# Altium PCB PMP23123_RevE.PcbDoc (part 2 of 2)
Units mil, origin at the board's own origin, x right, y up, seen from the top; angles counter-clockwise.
Board outline 4000 x 3800 mil, 4 copper layers (Top Layer, Layer 1, Layer 2, Bottom Layer), stack 76 mil thick; 128 components, 55 nets, 360 pads, 207 vias.
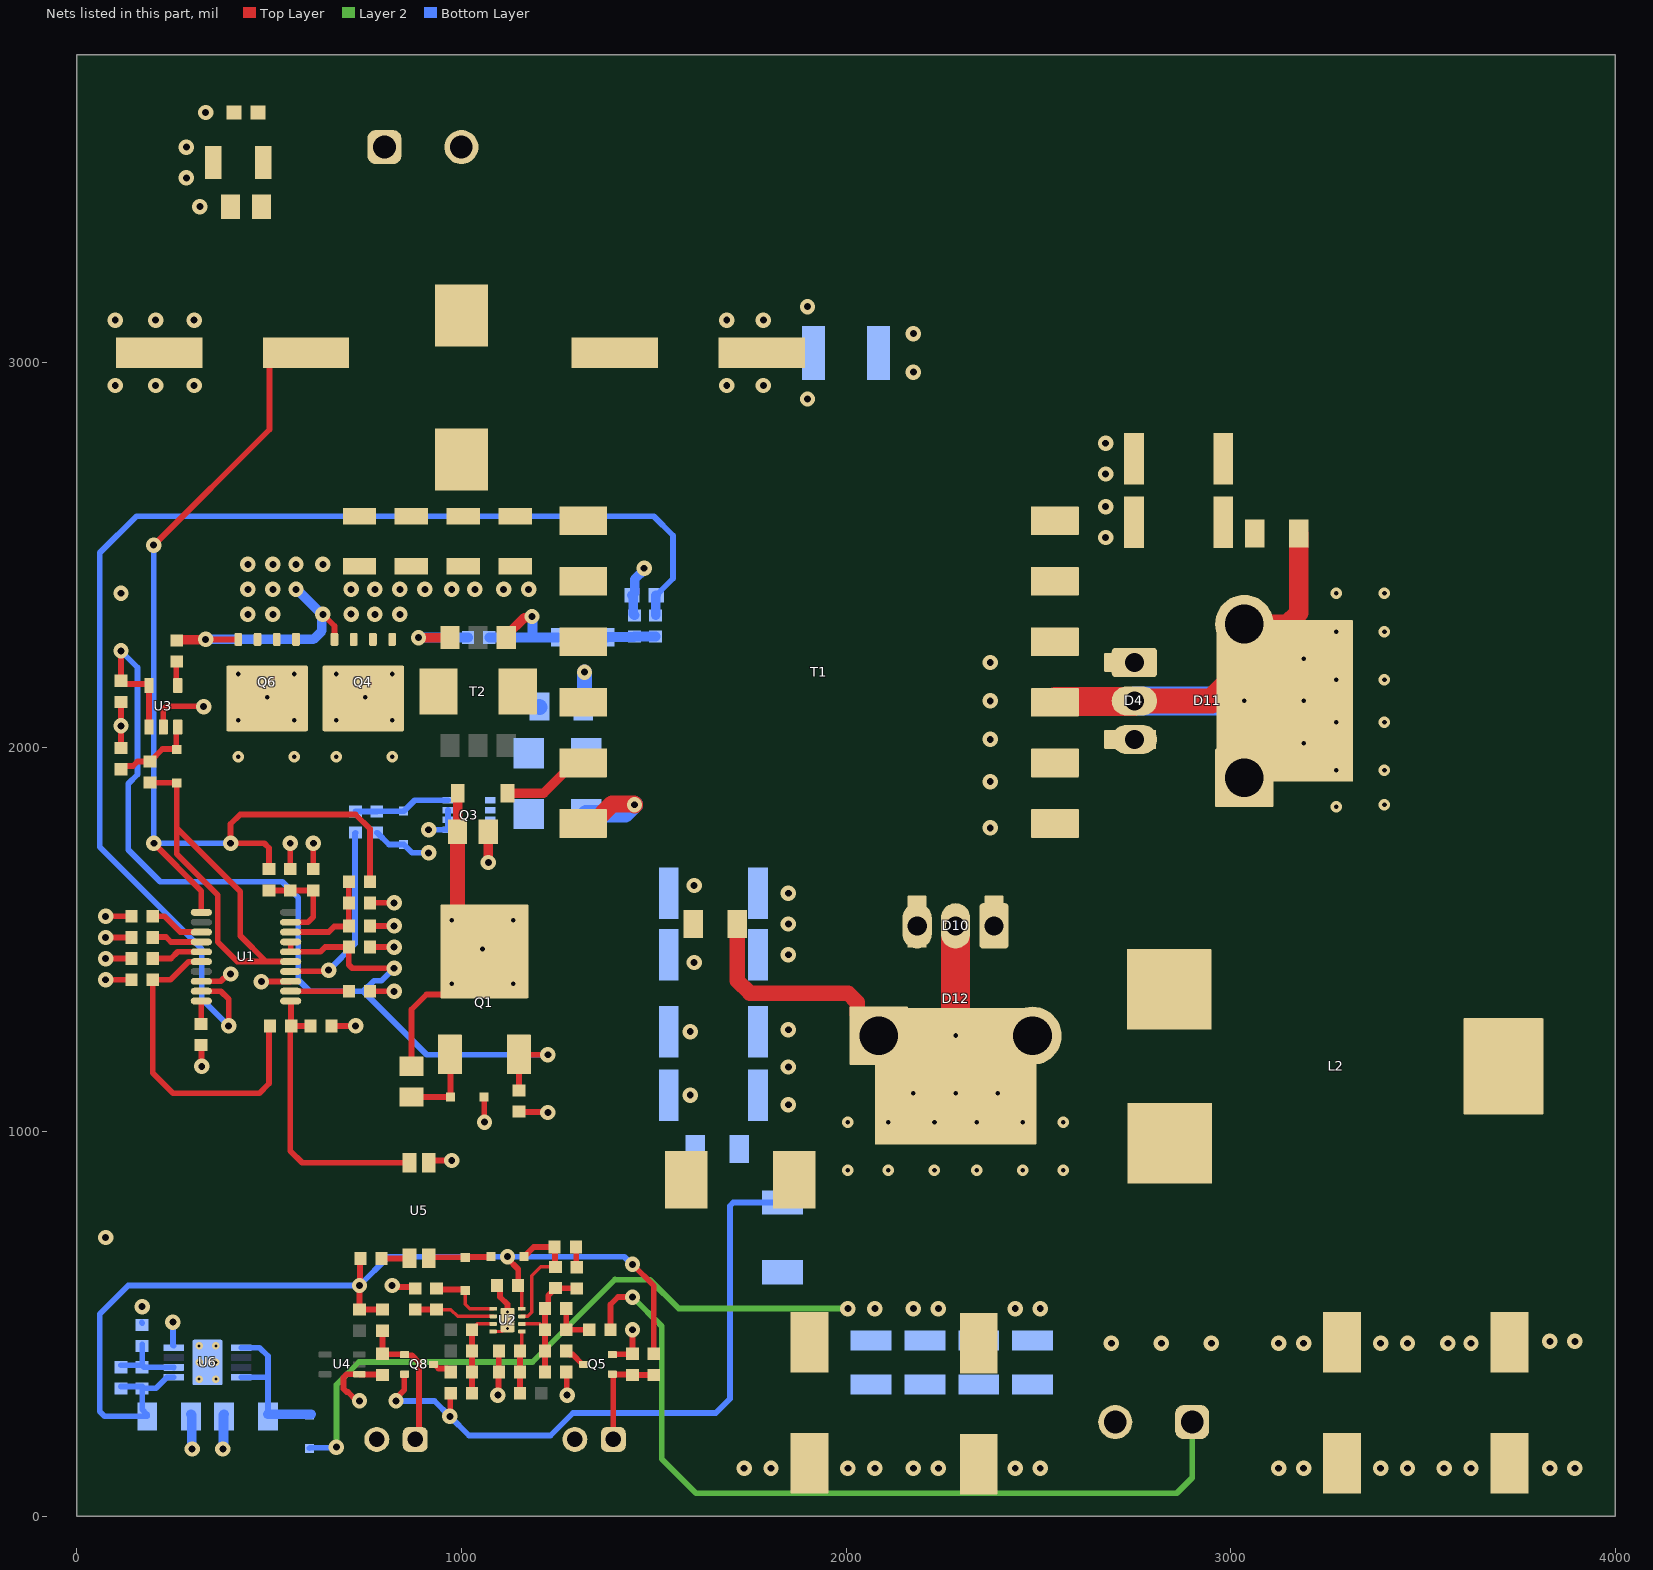
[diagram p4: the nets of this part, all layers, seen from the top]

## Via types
v1: diameter 40, hole 18, Top Layer to Bottom Layer, 148 vias
v2: diameter 30, hole 12, Top Layer to Bottom Layer, 51 vias
v3: diameter 19.68, hole 7.87, Top Layer to Bottom Layer, tented both sides, 4 vias
v4: diameter 19.68, hole 7.87, Top Layer to Bottom Layer, 4 vias

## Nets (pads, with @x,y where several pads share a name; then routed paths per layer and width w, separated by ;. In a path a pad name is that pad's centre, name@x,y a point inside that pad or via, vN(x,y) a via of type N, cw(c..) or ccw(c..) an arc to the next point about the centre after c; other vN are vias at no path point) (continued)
GND: C7.2 C8.2 C16.1 C17.1 C18.1 C19.1 C21.1 C30.2 C32.1 C37.1 C38.1 C100.2 C101.2 J2.2 J3.2 J4.2 L2.1 Q5.2 R3.2 R16.2 R18.2 R21.2 R30.2 R33.2 R36.2 U2.4 U2.9 U4.1 U6.4 U6.9@340,400 | length 913.7
  Top Layer w9: U2.4@1082.6,480.47 1104.25,480.47 1112.13,488.35 v4(1120,488.35)
  Top Layer w15: v1(735,300) 728.24,300 705.18,323.06 702.01,323.06 693.23,331.84 693.23,360.62 702.01,369.41 U4.1@734.29,369.41 734.63,369.41 735,369.04 793.41,369.04 R33.2@795,367.44 ; v1(820,600) 823.72,596.28 876.28,596.28 R30.2@880,592.56 ; C37.1@1092.44,600 1100.69,591.75 1100.69,570.48 1120,551.17 v4(1120,531.65) ; v1(1095,315) 1096.22,316.22 1096.22,373.78 C30.2@1097.44,375 R21.2@1097.44,430 ; R16.2@1272.56,375 1273.78,373.78 1273.78,316.22 v1(1275,315) ; Q5.2@1392.4,420.59 1393.39,421.57 1444.02,421.57 R18.2@1445,422.56 v1(1445,485)
  Bottom Layer w15: R36.2@168.78,503.78 R36.2@170,502.56 ; v1(250,505) 250,444.74 251.36,443.39 U6.4@252.4,443.39
  Bottom Layer w25: C38.1@297.09,265 298.54,263.54 298.54,176.46 v1(300,175) ; v1(380,175) 381.46,176.46 381.46,263.54 C32.1@382.91,265
  other v1: 1735,125 1805,125 2005,125 2075,125 2175,125 2240,125 2440,125 2505,125 3125,125 3190,125 3390,125 3460,125 3555,125 3625,125 3830,125 3895,125 170,545 75,725 2175,2975 2175,3075
  other v3: 318.35,356.69 361.65,356.69 318.35,443.31 361.65,443.31
  other v4: 318.35,400 361.65,400
ISNS: C41.1 D4.1 D4.3 D10.1 D10.3 D11.1 D11.3 D12.1 D12.3 Q8.2 R3.1 R34.2 R37.2 R38.2 R39.2 R40.2 R41.2 R42.2 T1.8 T1.10 T1.11 T1.12 | length 1726.6
  Top Layer w15: v1(830,300) 830,306.76 851.61,328.38 851.61,368.43 Q8.2@852.6,369.41 ; v1(970,260) 971.22,261.22 971.22,318.78 R34.2@972.44,320
  Bottom Layer w15: v1(830,300) 930,300 v1(970,260) 1020,210 1231.52,210 1289.86,268.35 1661.22,268.35 1698.31,305.43 1698.31,806.76 1707.09,815.55 R3.1@1835,815.55
  other v1: 1850,1070 1850,1168.34 1850,1265 1850,1460 1850,1540 1850,1620 2375,1790 2375,1910 2375,2020 2375,2120 2375,2220 2675,2545 2675,2625 2675,2710 2675,2790
NetC2_1: C2.1 U1.12 | length 151.5
  Top Layer w15: U1.12@556.14,1365.43 556.36,1365.22 707.22,1365.22 C2.1@707.44,1365
NetC3_2: C3.2 D1.1 Q1.2 R1.2 | length 734.3
  Top Layer w15: R1.2@870,1170 870,1317.48 909.11,1356.59 953.33,1356.59 Q1.2@1060,1463.27
  Top Layer w25: C3.2@990,1780 990.27,1780.27 990.27,1879.73 D1.1@990.53,1880
  Top Layer w40: v2(975,1550) 990,1565 C3.2@990,1780
  other v2: 975,1385 1135,1385 1055,1475 1135,1550
NetC12_2: C12.2 C13.2 C14.2 C15.2 L1.2 T1.1 T1.2
NetC20_1: C20.1 T1.3 T1.4 T2.8 | length 91.2
  Bottom Layer w40: C20.1@1317.09,2105 1320,2107.91 v1(1320,2195)
NetC20_2: C20.2 D13.1 D14.2 | length 1.5
  Bottom Layer w40: C20.2@1202.91,2105 C20.2@1203.96,2103.96
NetC22_1: C22.1 D6.2 Q3.4 R9.1 | length 252.1
  Bottom Layer w15: C22.1@725,1832.56 R9.1@780,1832.56 780.37,1832.93 849.63,1832.93 D6.2@850,1833.31 878.46,1861.77 Q3.4@965,1861.77
NetC22_2: C22.2 U1.14 | length 486.7
  Top Layer w15: U1.14@556.14,1416.61 556.66,1417.13 652.13,1417.13 v1(655,1420)
  Bottom Layer w15: v1(655,1420) 723.66,1488.66 723.66,1776.1 C22.2@725,1777.44
NetC23_2: C23.2 R5.1 R10.1 U1.19 | length 248.8
  Top Layer w15: R5.1@500,1627.44 R10.1@555,1627.44 C23.2@615,1627.44 615,1558.03 601.54,1544.57 U1.19@556.14,1544.57
NetC24_2: C24.2 R6.1 R14.1 U1.18 | length 272.9
  Top Layer w15: U1.18@556.14,1518.98 655.12,1518.98 669.45,1533.31 705.75,1533.31 C24.2@707.44,1535 R14.1@707.44,1595 R6.1@707.44,1650
NetC25_1: C25.1 C27.1 C102.1 R7.2 R12.1 R16.1 U2.6 | length 351.3
  Top Layer w9: U2.6@1157.4,500.16 1203.27,500.16 R7.2@1217.44,485.98
  Top Layer w15: R16.1@1217.44,375 R12.1@1217.44,430 R7.2@1217.44,485 1217.44,485.98 C102.1@1217.44,540 1225.69,548.25 1225.69,573.8 1235.77,583.88 1235.77,584.86 1244.02,593.11 C25.1@1245,593.11 1245.33,592.78 1299.67,592.78 C27.1@1300,592.44
NetC25_2: C25.2 D8.1 R17.1 U2.7 | length 338.3
  Top Layer w9: U2.7@1157.4,519.84 1157.82,520.26 1172.51,520.26 1182.8,530.55 1182.8,625.85 1206.28,649.33 C25.2@1243.9,649.33
  Top Layer w15: D8.1@1163.31,675 1188.31,700 R17.1@1242.44,700 1243.72,698.72 1243.72,649.51 1243.9,649.33 C25.2@1245,648.23
NetC26_2: C26.2 R2.2 U1.9 | length 3295.1
  Top Layer w15: U1.9@323.86,1365.43 374.57,1365.43 395,1345 v1(395,1275)
  Bottom Layer w15: v1(395,1275) 325,1345 325,1475 60,1740 60,2505 154.96,2599.96 1500.04,2599.96 1550,2550 1550,2438.5 1518.68,2407.19 1518.68,2406.2 1507.48,2395 C26.2@1506.5,2395
  Bottom Layer w25: R2.2@1505,2342.56 1505.75,2343.31 1505.75,2394.25 C26.2@1506.5,2395
NetC27_2: C27.2 R17.2 | length 53.5
  Top Layer w15: R17.2@1297.56,700 1298.78,698.78 1298.78,648.78 C27.2@1300,647.56
NetC28_2: C28.2 R28.1 U1.11 U5.4 | length 764.2
  Top Layer w15: U1.11@556.14,1339.84 556.85,1339.13 556.85,1275.71 R28.1@557.56,1275 ; C28.2@607.44,1275 R28.1@557.56,1275 ; U5.4@865,919.02 585.98,919.02 555,950 555,1272.44 R28.1@557.56,1275
NetC30_1: C30.1 R19.1 R21.1 U2.5 | length 162.5
  Top Layer w9: R21.1@1152.56,430 1157.4,434.84 U2.5@1157.4,480.47
  Top Layer w15: R19.1@1152.44,320 1152.5,320.06 1152.5,374.94 C30.1@1152.56,375 R21.1@1152.56,430
NetC31_1: C31.1 D7.2 R26.2 U3.3 | length 229.1
  Top Layer w15: C31.1@115,1942.44 123.25,1950.69 145.89,1950.69 157.76,1962.56 R26.2@190,1962.56 190.98,1962.56 223.21,1994.78 258.52,1994.78 D7.2@258.7,1994.61 ; U3.3@258.7,2054.57 D7.2@258.7,1994.61 ; D7.2@260,1993.31 D7.2@258.7,1994.61 ; U3.3@261.83,2051.44 U3.3@263.13,2050.14
NetC32_2: C32.2 D100.1 U6.5 U6.8 | length 411.8
  Bottom Layer w15: U6.8@427.6,361.61 496.63,361.61 497.13,362.11 ; U6.5@427.6,438.39 475.35,438.39 497.13,416.61 497.13,362.11 ; C32.2@497.13,264.96 497.13,362.11
  Bottom Layer w25: C32.2@497.13,264.96 D100.1@609,264.96
NetC33_2: C33.2 R28.2 U1.6 | length 873.9
  Top Layer w15: U1.6@323.86,1442.2 323.34,1441.68 290.59,1441.68 243.9,1395 C33.2@197.56,1395 197.56,1152.44 250,1100 475,1100 500,1125 500,1272.56 R28.2@502.44,1275
NetC34_1: C34.1 R30.1 U2.2 | length 210
  Top Layer w9: C34.1@935,537.44 935.12,537.56 972.44,537.56 990.16,519.84 U2.2@1082.6,519.84
  Top Layer w15: R30.1@880,537.44 C34.1@935,537.44
NetC34_2: C34.2 D9.1 U2.1 | length 190.3
  Top Layer w9: D9.1@1010,586.69 1010,551.34 1021.81,539.53 U2.1@1082.6,539.53
  Top Layer w15: C34.2@935,592.56 937.93,589.63 1007.07,589.63 D9.1@1010,586.69
NetC35_2: C35.2 R29.1 R36.1 U6.2 | length 194.5
  Bottom Layer w15: C35.2@115,392.56 R29.1@170,392.56 ; R36.1@170,447.44 R36.1@170,442.44 R29.1@170,392.56 ; U6.2@252.4,387.2 252.22,387.38 175.18,387.38 R29.1@170,392.56
NetC36_1: C36.1 R32.2 R34.1 R35.2 U2.3 | length 226.9
  Top Layer w9: C36.1@1027.56,485 1027.56,485.98 1041.73,500.16 U2.3@1082.6,500.16
  Top Layer w15: R34.1@1027.56,320 R32.2@1027.56,375 R35.2@1027.56,430 C36.1@1027.56,485
NetC39_1: C39.1 R37.1 R38.1
NetC40_1: C40.1 R39.1 R40.1
  other v1: 1605,1440 1605,1640
NetC41_2: C41.2 D2.1 R41.1 R42.1
  other v1: 1595,1095 1595,1260
NetC102_2: C102.2 R4.1 R7.1 | length 114.9
  Top Layer w15: C102.2@1272.56,540 R7.1@1272.56,485 R4.1@1332.44,485
NetD1_2: D1.2 T1.5 | length 230
  Top Layer w25: D1.2@1119.47,1880 1213.43,1880 1292.2,1958.78 T1.5@1316.81,1958.78
NetD3_1: D3.1 Q1.1 R1.1 | length 213.4
  Top Layer w15: R1.1@870,1090 D3.1@971.69,1090 971.69,1199.68 Q1.1@970.24,1201.14
NetD5_1: D5.1 R2.1 R11.1 | length 126.5
  Bottom Layer w25: D5.1@1379.47,2285 1380.69,2286.22 1448.78,2286.22 R11.1@1450,2287.44 R2.1@1505,2287.44
NetD5_2: D5.2 R8.2 T2.1 | length 325.7
  Top Layer w25: T2.1@1116.5,2284.45 1116.5,2289.45 1163.63,2336.58 1180.63,2336.58 v1(1183.5,2339.45)
  Bottom Layer w25: R8.2@1072.56,2285 1185,2285 ; v1@1185,2340 1185,2285 ; D5.2@1250.53,2285 1185,2285
NetD7_1: D7.1 R26.1 U1.15 | length 1180.8
  Top Layer w15: R26.1@190,1907.44 190.37,1907.07 259.63,1907.07 D7.1@260,1906.69 260,1789.8 ; U1.15@555.62,1442.72 491.73,1442.72 ; 260,1789.8 260,1722.35 366.79,1615.56 366.79,1493.23 417.3,1442.72 491.73,1442.72 ; 260,1789.8 425,1624.8 425,1509.45 491.73,1442.72
NetD8_2: D8.2 D9.2 U5.2 | length 163.4
  Top Layer w15: U5.2@915,670.98 917.32,673.31 D9.2@1010,673.31 1010.85,674.15 1075.85,674.15 D8.2@1076.69,675
NetD13_2: D13.2 Q3.5 Q3.6 Q3.7 Q3.8
NetJ3_1: J3.1 Q5.1 R15.2 R18.1 | length 277.2
  Top Layer w15: Q5.1@1392.4,369.41 1393.25,369.41 Q5.1@1394.23,368.43 ; J3.1@1395,200 1395,367.66 Q5.1@1394.23,368.43 ; R15.2@1500,367.44 R18.1@1445,367.44 1444.02,368.43 Q5.1@1394.23,368.43
NetJ4_1: J4.1 Q8.1 R31.2 R33.1 | length 368.4
  Top Layer w15: R31.2@795,482.44 R33.1@795,422.56 795.98,421.57 851.61,421.57 Q8.1@852.6,420.59 854.35,418.84 871.16,418.84 890,400 890,210 J4.1@880,200
NetQ4_4: Q4.4 Q6.4 R24.1 | length 690.7
  Top Layer w15: v1(335,2280) Q6.4@420,2280 ; v1(640,2345) 670,2315 Q4.4@670,2280
  Top Layer w25: R24.1@260,2277.56 261.22,2278.78 333.78,2278.78 v1(335,2280)
  Bottom Layer w25: v1(335,2280) 615,2280 637.13,2302.13 637.13,2342.13 v1(640,2345) 637.5,2345 572.5,2410 v1(570,2410)
NetQ4_5: Q4.5 Q4.6 Q4.7 Q4.8 Q4.9@745,2126.46 Q6.5 Q6.6 Q6.7 Q6.8 Q6.9@495,2126.46 T2.7
  other v2: 420,1975 565,1975 675,1975 820,1975 420,2070 565,2070 675,2070 820,2070 495,2130 750,2130 420,2190 565,2190 675,2190 820,2190
NetQ5_3: Q5.3 R12.2 | length 60.1
  Top Layer w15: R12.2@1272.56,430 1272.56,429.02 1280.81,420.77 1289.27,420.77 1315.04,395 Q5.3@1317.6,395
NetQ8_3: Q8.3 R32.1 | length 53.9
  Top Layer w15: Q8.3@927.4,395 929.96,395 940.73,384.23 964.19,384.23 972.44,375.98 R32.1@972.44,375
NetR13_1: R13.1 U1.3 | length 143.3
  Top Layer w15: R13.1@197.56,1560 228.31,1560 269.33,1518.98 U1.3@323.86,1518.98
NetR20_2: R20.2 U1.4 | length 131.9
  Top Layer w15: R20.2@197.56,1505 198.51,1505.95 232.24,1505.95 244.81,1493.39 U1.4@323.86,1493.39
NetR23_2: R23.2 U1.5 | length 133.7
  Top Layer w15: R23.2@197.56,1450 244.81,1450 262.6,1467.8 U1.5@323.86,1467.8
NetR24_2: R24.2 U3.4 | length 59.4
  Top Layer w15: U3.4@258.7,2165.43 258.7,2221.14 R24.2@260,2222.44 ; U3.4@261.83,2159.71 U3.4@263.13,2161.01
NetR25_2: R25.2 U1.10 | length 59.9
  Top Layer w15: R25.2@323.34,1280.31 323.6,1280.57 323.6,1339.58 U1.10@323.86,1339.84 U1.10@323.78,1339.92
NetR27_2: R27.2 U5.1 | length 72.8
  Top Layer w15: R27.2@792.56,670 864.02,670 U5.1@865,670.98
P_BIAS: C1.2 C4.2 C29.1 Q1.3 U1.16 U1.17 U3.1 U3.5 | length 2861
  Top Layer w15: v1(115,2250) 115,2173.54 124.41,2164.13 182.6,2164.13 U3.5@183.25,2163.48 ; U3.1@187.67,2052.09 U3.5@187.67,2159.06 ; U1.17@556.14,1493.39 U1.16@556.14,1467.8 633.7,1467.8 645.91,1480 C4.2@707.44,1480 707.44,1433.79 716.23,1425 v1(825,1425) ; Q1.3@1149.76,1201.14 Q1.3@1150,1200.91 ; C1.2@1150,1107.56 Q1.3@1150,1200.91 ; v1(1225,1200) 1150.91,1200 Q1.3@1150,1200.91
  Bottom Layer w15: v1(115,2250) 157.76,2207.24 157.76,1928.66 133.7,1904.61 133.7,1733.06 216.76,1650 534.33,1650 575.67,1608.66 575.67,1395 605.67,1365 745,1365 ; v1(825,1425) 792.61,1392.61 772.61,1392.61 745,1365 ; v1(1225,1200) 910,1200 745,1365
PGND: C1.1 C2.2 C3.1 C4.1 C5.2 C6.2 C9.1 C10.1 C11.1 C12.1 C13.1 C14.1 C15.1 C21.2 C23.1 C24.1 C26.1 C28.1 C29.2 C31.2 C33.1 D3.2 D6.1 D14.1 J1.2 Q3.1 Q3.2 Q3.3 Q4.1 Q4.2 Q4.3 Q6.1 Q6.2 Q6.3 R8.1 R9.2 R10.2 R11.2 R13.2 R14.2 R20.1 R23.1 R25.1 T1.6 T2.3 U1.8 U1.13 U3.2 U5.3 | length 2471
  Top Layer w10: R20.1@135.55,1511.89 R20.1@142.44,1505 ; C13.1@850,2472.87 852.83,2470.04 C13.1@870,2470.04 879.96,2480 C13.1@889.68,2480 ; C14.1@1005,2470.04 1006.97,2472.01 C14.1@1024.68,2472.01
  Top Layer w15: v1(75,1395) C33.1@142.44,1395 ; v1(75,1450) R23.1@142.44,1450 ; v1(75,1505) R20.1@142.44,1505 ; v1(75,1560) R13.2@142.44,1560 ; C31.2@115,1997.56 v1(115,2055) ; C29.2@115,2117.44 v1(115,2055) ; v1@115.43,2055.43 v1(115,2055) ; U3.2@225.07,2052.09 225.07,2097.37 233.93,2106.22 v1@325.47,2106.22 ; 307.09,2106.22 v1@325.47,2106.22 ; R25.1@323.34,1225.2 324.17,1224.37 324.17,1170.83 v1(325,1170) ; U1.8@323.86,1391.02 374.26,1391.02 393.24,1410 v1(400,1410) ; v1@328.2,2103.49 v1@325.47,2106.22 ; v1(480,1390) 480.51,1390.51 555.63,1390.51 U1.13@556.14,1391.02 ; R10.2@555,1682.56 v1(555,1750) ; C23.1@615,1682.56 v1(615,1750) ; C28.1@662.56,1275 v1(725,1275) ; C2.2@762.56,1365 v1(825,1365) ; C4.1@762.56,1480 v1(825,1480) ; C24.1@762.56,1535 v1(825,1535) ; R14.2@762.56,1595 v1(825,1595) ; U5.3@915,919.02 920.98,925 v1(975,925) ; D3.2@1058.31,1090 1059.15,1089.15 1059.15,1025.85 v1(1060,1025) ; C1.1@1150,1052.44 1151.22,1051.22 1223.78,1051.22 v1(1225,1050)
  Top Layer w25: v1(888.5,2284.45) T2.3@970.5,2284.45 ; v1(1070,1700) C3.1@1070,1780
  Top Layer w45: T1.6@1316.81,1801.3 1341.42,1801.3 1392.36,1852.24 1447.76,1852.24 v1(1450,1850)
  Bottom Layer w15: R9.2@780,1777.44 780.98,1777.44 811.73,1746.69 D6.1@850,1746.69 871.69,1725 v1(915,1725) ; v1(915,1785) Q3.1@965,1785 Q3.2@965,1810.59 Q3.3@965,1836.18
  Bottom Layer w25: v1@900,2285 R8.1@1017.44,2285 ; R11.2@1450,2342.56 1446.75,2345.81 1446.75,2391.75 C26.1@1443.5,2395 1444.49,2395 1450.69,2401.2 1450.69,2436.63 1475,2460.94 v1(1475,2465)
  Bottom Layer w45: D14.1@1325,1826.26 1426.26,1826.26 v1(1450,1850)
  other v1: 330,2105 445,2345 510,2345 775,2345 840,2345 713.35,2345.81 115,2400 445,2410 510,2410 713.35,2410 775,2410 840,2410 905,2410 975,2410 1035,2410 1110,2410 1175,2410 445,2475 510,2475 570,2475 640,2475 1900,2905 100,2940 205,2940 305,2940 1690,2940 1785,2940 100,3110 205,3110 305,3110 1690,3110 1785,3110 1900,3145 320,3405 285,3480 285,3560 335,3650
S_BIAS: C35.1 C37.2 C38.2 R15.1 R22.1 R27.1 R29.2 R31.1 U2.8 U6.1 | length 2667.6
  Top Layer w9: C37.2@1147.56,600 1157.4,590.16 U2.8@1157.4,539.53
  Top Layer w15: R27.1@737.44,670 736.22,668.78 736.22,601.22 v1(735,600) R22.1@735,537.56 R31.1@795,537.56 ; v1(1120,675) 1120,670.01 1147.56,642.45 C37.2@1147.56,600 ; v1(1445,655) 1500,600 1500,501.46 ; R15.1@1500,422.56 1500,501.46 ; 1501.46,500 1500,501.46
  Bottom Layer w15: C35.1@115,337.44 R29.2@170,337.44 ; C38.2@182.91,260 72.37,260 60,272.37 60,526.3 133.7,600 v1(735,600) 810,675 1423.71,675 1443.71,655 v1(1445,655) ; C38.2@182.91,265 170,277.91 R29.2@170,332.44 R29.2@170,337.44 ; U6.1@252.4,361.61 234.69,361.61 205.85,332.78 174.66,332.78 R29.2@170,337.44
VIN: C5.1 C6.1 C9.2 C10.2 C11.2 J1.1 L1.1 R5.2 R6.2 U1.1 | length 2642.7
  Top Layer w15: v1(200,2525) 501.02,2826.02 501.02,2993.13 532.89,3025 C6.1@595.94,3025 ; v1(200.31,1750) 200.31,1749.69 323.86,1626.14 U1.1@323.86,1570.16 ; R5.2@500,1682.56 500,1737.32 487.32,1750 v1(400,1750) 400,1800 425,1825 725,1825 762.56,1787.44 R6.2@762.56,1650
  Bottom Layer w15: v1(200,2525) 200.31,2524.69 v1(200.31,1750) v1(400,1750)
VOUT: C7.1 C8.1 C16.2 C17.2 C18.2 C19.2 C100.1 C101.1 D100.2 J2.1 L2.3 R4.2 | length 3869.4
  Top Layer w15: R4.2@1387.56,485 1387.56,550.36 1407.2,570 v1(1445,570)
  Layer 2 w15: v1(675,180) 675,341.85 734.06,400.91 1184.81,400.91 1399.29,615.39 1490,615 1565,540 v1(2005,540) ; v1(1445,570) 1520.67,494.33 1520.67,149.33 1610,60 2860,60 2900,100 J2.1@2900,245 ; v1(2820,450) v1@2820.98,450
  Bottom Layer w15: D100.2@605,176.69 606.65,178.35 673.35,178.35 v1(675,180)
  other v1: 2690,450 2950,450 3125,450 3190,450 3390,450 3460,450 3565,450 3625,450 3830,455 3895,455 2075,540 2175,540 2240,540 2440,540 2505,540
VSEC_A: C40.2 D2.2 D10.2 D12.2 H2.1 H2.2 L2.2 T1.7 | length 1443.5
  Top Layer w40: C40.2@1717.09,1540 1717.09,1392.91 1750,1360 2005.78,1360 2029.21,1336.57 2029.21,1305.04 H2.1@2085,1249.25
  Top Layer w75: D12.2@2285,1144.49 D10.2@2285,1535
  Bottom Layer w75: D10.2@2285,1535 2285,1293.19 2328.93,1249.25 H2.2@2485,1249.25
  other v2: 2005,900 2110,900 2230,900 2340,900 2460,900 2565,900 2005,1025 2110,1025 2230,1025 2340,1025 2460,1025 2565,1025 2175,1100 2285,1100 2395,1100 2285,1250
VSEC_B: C39.2 D4.2 D11.2 H1.1 H1.2 T1.9 | length 1457.2
  Top Layer w50: H1.2@3035.75,2320 3147.8,2320 3177.09,2349.29 C39.2@3177.09,2555
  Top Layer w65: T1.9@2543.19,2116.26 T1.9@2545.06,2118.13 ; D4.2@2748.13,2118.13 D4.2@2750,2120 2950.75,2120 3035.75,2205 H1.2@3035.75,2320
  Top Layer w75: T1.9@2545.06,2118.13 D4.2@2748.13,2118.13
  Bottom Layer w75: D4.2@2750,2120 2981.04,2120 3024.98,2163.93 3024.98,2309.23 H1.2@3035.75,2320
  other v2: 3275,1845 3400,1850 3275,1940 3400,1940 3190,2010 3275,2065 3400,2065 3035,2120 3190,2120 3275,2175 3400,2175 3190,2230 3275,2300 3400,2300 3275,2400 3400,2400
pads on no net: Q4.9@651.59,2201.65 Q4.9@692.64,2099.49 Q4.9@692.64,2144.76 Q4.9@692.64,2190.04 Q4.9@745,2099.49 Q4.9@745,2139.45 Q4.9@745,2144.76 Q4.9@745,2190.04 Q4.9@797.36,2099.49 Q4.9@797.36,2144.76 Q4.9@797.36,2190.04 Q4.9@838.41,2201.65 Q6.9@401.59,2201.65 Q6.9@442.64,2099.49 Q6.9@442.64,2144.76 Q6.9@442.64,2190.04 Q6.9@495,2099.49 Q6.9@495,2139.45 Q6.9@495,2144.76 Q6.9@495,2190.04 Q6.9@547.36,2099.49 Q6.9@547.36,2144.76 Q6.9@547.36,2190.04 Q6.9@588.41,2201.65 T2.2 T2.4 T2.5 T2.6 U1.2 U1.7 U1.20 U4.2 U4.4 U4.5 U6.3 U6.6 U6.7 U6.9@340,400

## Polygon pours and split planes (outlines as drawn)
ISNS on Top Layer "TOP_LAYER_ISNS_P049" (solid, remove dead copper, pour order 49): 1915,1290 1915,1045 1735,1045 1735,1290
PGND on Top Layer "TOP_LAYER_PGND_P054" (solid, remove dead copper, pour order 54): 50,3750 1950,3750 1950,1800 1400,1800 1400,850 50,850
NetC40_1 on Top Layer "TOP_LAYER_NETC40_1_P014" (solid, remove dead copper, pour order 14): 1630,1385 1500,1385 1500,1700 1630,1700
GND on Top Layer "TOP_LAYER_GND_P051" (solid, remove dead copper, pour order 51): 50,750 1450,750 1450,600 3000,600 3000,1300 3000,1745 3600,1745 3600,2400 2900,2400 2900,2800 2050,2800 2050,3750 3950,3750 3950,50 50,50
ISNS on Top Layer "TOP_LAYER_ISNS_P043" (solid, remove dead copper, pour order 43): 1690,1700 1690,1520 1790,1520 1790,1430 1920,1430 1920,1450 2220,1450 2220,1680 2350,1680 2350,1450 2425,1450 2425,1890 2825,1890 2825,2055 2430,2055 2430,2185 2825,2185 2825,2850 2050,2850 2050,1700
NetC3_2 on Top Layer "TOP_LAYER_NETC3_2_P013" (solid, remove dead copper, pour order 13): 895,1340 895,1650 1225,1650 1225,1340
ISNS on Top Layer "TOP_LAYER_ISNS_P038" (solid, remove dead copper, pour order 38): 2650,2185 2650,2255 2815,2255 2815,2185
ISNS on Top Layer "TOP_LAYER_ISNS_P018" (solid, remove dead copper, pour order 18): 2650,1985 2815,1985 2815,2055 2650,2055
ISNS on Top Layer "TOP_LAYER_ISNS_P016" (solid, remove dead copper, pour order 16): 2420,1630 2350,1630 2350,1470 2420,1470
ISNS on Top Layer "TOP_LAYER_ISNS_P015" (solid, remove dead copper, pour order 15): 2150,1630 2150,1470 2220,1470 2220,1630
VSEC_A on Top Layer "TOP_LAYER_VSEC_A_P004" (solid, remove dead copper, pour order 4): 1810,750 1810,995 1965,995 1965,1390 2475,1390 2475,1840 2825,1840 2825,1750 2950,1750 2950,1220 2605,1220 2605,750
NetC41_2 on Top Layer "TOP_LAYER_NETC41_2_P010" (solid, remove dead copper, pour order 10): 1685,1335 1685,750 1500,750 1500,1335
NetC39_1 on Top Layer "TOP_LAYER_NETC39_1_P009" (solid, remove dead copper, pour order 9): 3090,2500 2900,2500 2900,2850 3090,2850
VOUT on Top Layer "TOP_LAYER_VOUT_P008" (solid, remove dead copper, pour order 8): 2950,1160 2950,575 3950,575 3950,315 2975,315 2975,185 2825,185 2825,340 1675,340 1675,700 2525,700 2650,700 2650,1160
VSEC_B on Top Layer "TOP_LAYER_VSEC_B_P005" (solid, remove dead copper, pour order 5): 2895,1800 3550,1800 3550,2450 2895,2450
NetQ4_5 on Top Layer "TOP_LAYER_NETQ4_5_P003" (solid, remove dead copper, pour order 3): 995,2210 385,2210 385,1900 855,1900 855,2080 995,2080
NetC20_1 on Top Layer "TOP_LAYER_NETC20_1_P002" (solid, remove dead copper, pour order 2): 1095,2210 1250,2210 1250,2315 1400,2315 1400,2080 1095,2080
VIN on Top Layer "TOP_LAYER_VIN_P001" (solid, remove dead copper, pour order 1): 1550,2900 450,2900 450,3750 850,3750 850,3400 1550,3400
NetC12_2 on Top Layer "TOP_LAYER_NETC12_2_P000" (solid, remove dead copper, pour order 0): 1400,2390 1250,2390 1250,2570 670,2570 670,2850 1400,2850
VOUT on Bottom Layer "BOTTOM_LAYER_VOUT_P052" (solid, pour order 52): 1965,575 1965,700 2625,700 2625,575 3950,575 3950,315 2975,315 2975,185 2825,185 2825,400 1965,400
NetC40_1 on Bottom Layer "BOTTOM_LAYER_NETC40_1_P047" (solid, remove dead copper, pour order 47): 1640,1700 1640,1385 1500,1385 1500,1700
NetC41_2 on Bottom Layer "BOTTOM_LAYER_NETC41_2_P044" (solid, remove dead copper, pour order 44): 1500,1335 1500,750 1640,750 1640,1335
PGND on Bottom Layer "BOTTOM_LAYER_PGND_P056" (solid, remove dead copper, pour order 56): 50,3750 1950,3750 1950,1800 1400,1800 1400,850 50,850
NetC3_2 on Bottom Layer "BOTTOM_LAYER_NETC3_2_P042" (solid, remove dead copper, pour order 42): 1225,1340 1225,1650 895,1650 895,1340
GND on Bottom Layer "BOTTOM_LAYER_GND_P053" (solid, remove dead copper, pour order 53): 50,750 1450,750 1450,700 2650,700 2650,1400 2875,1400 2875,1750 3600,1750 3600,2500 2900,2500 2900,2900 2050,2900 2050,3750 3950,3750 3950,50 50,50
VSEC_B on Bottom Layer "BOTTOM_LAYER_VSEC_B_P041" (solid, remove dead copper, pour order 41): 2895,2450 3550,2450 3550,1800 2895,1800
VSEC_A on Bottom Layer "BOTTOM_LAYER_VSEC_A_P040" (solid, remove dead copper, pour order 40): 1965,750 1965,1390 2610,1390 2610,750
ISNS on Bottom Layer "BOTTOM_LAYER_ISNS_P039" (solid, remove dead copper, pour order 39): 1690,750 1690,970 1690,1700 2050,1700 2050,2850 2825,2850 2825,1450 1915,1450 1915,750
VOUT on Bottom Layer "BOTTOM_LAYER_VOUT_P031" (solid, remove dead copper, pour order 31): 3050,1240 2830,1240 2830,690 3050,690
NetC20_2 on Bottom Layer "BOTTOM_LAYER_NETC20_2_P024" (solid, remove dead copper, pour order 24): 1380,1945 1115,1945 1115,2150 1230,2150 1230,2025 1380,2025
NetD13_2 on Bottom Layer "BOTTOM_LAYER_NETD13_2_P023" (solid, remove dead copper, pour order 23): 1005,1760 1005,1890 1220,1890 1220,1760
NetQ4_5 on Bottom Layer "BOTTOM_LAYER_NETQ4_5_P021" (solid, remove dead copper, pour order 21): 855,1900 385,1900 385,2210 855,2210
GND on Layer 1 "LAYER_1_GND_P046" (solid, remove dead copper, pour order 46): 50,750 1500,750 1500,1700 2050,1700 2050,3750 3950,3750 3950,50 50,50
PGND on Layer 1 "LAYER_1_PGND_P050" (solid, pour order 50): 50,850 50,3750 1950,3750 1950,1800 1400,1800 1400,850
GND on Layer 2 "LAYER_2_GND_P048" (solid, remove dead copper, pour order 48): 50,750 1500,750 1500,1700 2050,1700 2050,3750 3950,3750 3950,50 50,50
PGND on Layer 2 "LAYER_2_PGND_P055" (solid, remove dead copper, pour order 55): 50,3750 1950,3750 1950,1800 1400,1800 1400,850 50,850

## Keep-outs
Keep-Out Layer:
  text ".Layer_Name" at 577,-858.49 h60

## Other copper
Top Layer:
  rectangle net GND: 1102.28,465 1135,492.28
  rectangle net GND: 1070,450 1110,485
  text ".Layer_Name" at 577,-858.49 h60
Bottom Layer:
  text ".Layer_Name" at 577,-858.49 h60

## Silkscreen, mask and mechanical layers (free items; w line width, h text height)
Top Overlay:
  text "VIN" at 632.35,3585.12 h60 r90
  text "PGND" at 1216,3520 h60 r90
  text "'.PRJ_Number'.PCB_Rev" at 2100,3500 h108.27
  text "GND" at 2596.56,540.34 h50
  text "VOUT" at 2879.16,540.34 h50
  text ".Layer_Name" at 577,-858.49 h60
Bottom Overlay:
  text ".Layer_Name" at 577,-858.49 h60
Top Paste:
  text ".Layer_Name" at 577,-858.49 h60
Bottom Paste:
  text ".Layer_Name" at 577,-858.49 h60
Top Solder:
  text ".Layer_Name" at 577,-858.49 h60
  text ".Layer_Name" at 577,-858.49 h60
Bottom Solder:
  text ".Layer_Name" at 577,-858.49 h60
Drill Guide:
  text ".Layer_Name" at 577,-858.49 h60
M1 Board Outline:
  the board outline again, w10
  text ".Layer_Name" at 577,-858.49 h60
M2 Board Dimensions:
  rectangle: 0,-275 125,-150
  rectangle: 125,-400 500,-275
  lines w7: 0,-275 1000,-275 ; 125,-400 125,-150 ; 250,-400 250,-150 ; 500,-400 500,-150 ; 750,-400 750,-150 ; 0,-400 1000,-400 1000,-150 0,-150 0,-400
  text ".Layer_Name" at 577,-858.49 h60
M3 3D STEP Top:
  text ".Layer_Name" at 577,-858.49 h60
M4 3D STEP Bottom:
  text ".Layer_Name" at 577,-858.49 h60
M5 Assembly Top:
  lines w10: -292,-930.17 6308,-930.17 ; -292,-726.83 6310,-726.83 ; -292,-523.5 -292,-1133.5 3713,-1133.5 6310,-1133.5 6310,-523.5 -291.5,-523.5 -291.5,-1133.5 1284,-1133.5 ; 2173,-1133.5 2173,-523.5 ; 3440,-726.83 3440,-523.5 ; 4280,-726.83 4280,-523.5 ; 4902,-1140 4902,-937.17
  text "COMPONENTS MARKED 'DNP' SHOULD NOT BE POPULATED." at 1153.5,-318.5 h60
  text "ASSEMBLY VARIANT:" at 1153,-434 h60
  text ".VariantName" at 2189,-434 h60
  text "PCB VIEWED FROM TOP SIDE" at -228.5,-655.67 h60
  text "BOARD #:" at 2248,-655.67 h60
  text ".PRJ_Number" at 2793.5,-655.67 h60
  text "REV:" at 3638,-655.67 h60
  text ".PCB_Rev" at 3929.5,-655.67 h60
  text "SVN REV:" at 4476,-655.67 h60
  text ".VersionControl_RevNumber" at 4982,-655.67 h60
  text "TID #:" at 2248,-859 h60
  text ".TID" at 2793.5,-859 h60
  text "PLOT NAME =" at -228.5,-1064.34 h60
  text ".plot_File_Name" at 577,-1064.34 h60
  text "GENERATED    :" at 2250,-1064.34 h60
  text ".Print_Date" at 3119.5,-1064.34 h60
  text ".Print_Time" at 3848.5,-1064.34 h60
  text "TEXAS INSTRUMENTS" at 5113,-1064.34 h60
M6 Assembly Bottom:
  lines w10: -292.5,-727.33 6309.5,-727.33 ; -290.5,-930.67 6309.5,-930.67 ; 1115.5,-1140.5 1115.5,-937.67 ; 1737.5,-727.33 1737.5,-524 ; 2577.5,-727.33 2577.5,-524 ; 3844.5,-1134 3844.5,-524 ; 4733.5,-1134 6309,-1134 6309,-524 -292.5,-524 -292.5,-1134 2304.5,-1134 6309.5,-1134 6309.5,-524
  text "COMPONENTS MARKED 'DNP' SHOULD NOT BE POPULATED." at 6102,-318 h60
  text ".VariantName" at 5058,-434 h60
  text "ASSEMBLY VARIANT:" at 6097,-434 h60
  text ".VersionControl_RevNumber" at 1035.5,-656.17 h60
  text "SVN REV:" at 1541.5,-656.17 h60
  text ".PCB_Rev" at 2088,-656.17 h60
  text "REV:" at 2379.5,-656.17 h60
  text ".PRJ_Number" at 3224,-656.17 h60
  text "BOARD #:" at 3769.5,-656.17 h60
  text "PCB VIEWED FROM BOTTOM SIDE" at 6246,-656.17 h60
  text ".TID" at 3224,-859.5 h60
  text "TID #:" at 3769.5,-859.5 h60
  text "TEXAS INSTRUMENTS" at 904.5,-1064.84 h60
  text ".Print_Time" at 2169,-1064.84 h60
  text ".Print_Date" at 2898,-1064.84 h60
  text "GENERATED    :" at 3767.5,-1064.84 h60
  text ".plot_File_Name" at 5440.5,-1064.84 h60
  text "PLOT NAME =" at 6246,-1064.84 h60
M9 Title Sheet:
  drawing of 57 lines, arcs and shapes, not listed
  text "1" at 739.84,8036.5 h70
  text "2" at 3235.5,8036.5 h70
  text "3" at 5724.84,8036.5 h70
  text "4" at 8231.51,8036.5 h70
  text "5" at 10730.5,8036.5 h70
  text "6" at 13235.5,8036.5 h70
  text "A" at -416.5,6893.5 h70
  text "A" at 14383.5,6893.5 h70
  text "B" at -416.5,4513.5 h70
  text "B" at 14383.5,4513.5 h70
  text "C" at -416.5,2138.5 h70
  text "C" at 14383.5,2138.5 h70
  text "PROJECT TITLE:" at 11343.5,277.5 h45
  text ".PRJ_Title" at 11393.5,144.17 h70
  text "DESIGNED FOR:" at 11343.5,-23.5 h45
  text ".PRJ_Customer" at 11393.5,-163.5 h70
  text "D" at -416.5,-231.5 h70
  text "D" at 14383.5,-231.5 h70
  text "FILE NAME:" at 11343.5,-323.5 h45
  text ".PCB_File_Name_No_Path" at 11393.5,-443.5 h70
  text "Texas Instruments (TI) and/or its licensors do not warrant the accuracy or completeness of this specification" at 6374,-605.34 h45
  text "ENGINEER:" at 11343.5,-613.5 h45
  text "LAYOUT BY:" at 12848.5,-613.5 h45
  text "or any information contained therein. TI and/or its licensors do not warrant that this design will meet" at 6329.01,-718 h45
  text ".PRJ_Engineer" at 11393.5,-768.49 h70
  text ".PCB_Layout" at 12899,-768.49 h70
  text "the specifications, will be suitable for your application or fit for any particular purpose, or will operate in" at 6329.01,-830.67 h45
  text ".Layer_Name" at 577,-858.49 h60
  text "ALTIUM DESIGNER VERSION:" at 12848.5,-923.5 h45
  text "an implementation. TI and/or its licensors do not warrant that the design is production worthy. You should" at 6329.01,-943.33 h45
  text "completely validate and test your design implementation to confirm the system functionality for your application." at 6374,-1056 h45
  text ".print_Scale" at 11393.5,-1056.83 h70
  text ".Application_BuildNumber" at 12899,-1056.83 h70
  text "1" at 739.84,-1263.5 h70
  text "2" at 3235.5,-1263.5 h70
  text "3" at 5724.84,-1263.5 h70
  text "4" at 8231.51,-1263.5 h70
  text "5" at 10730.5,-1263.5 h70
  text "6" at 13235.5,-1263.5 h70
M10 Fab Notes:
  drawing of 189 lines, arcs and shapes, not listed
  text "DESIGN INFORMATION" at 12382.02,6356.17 h60
  text "MIN. TRACK WIDTH:" at 11737.46,6224.05 h60
  text "8" at 12833.7,6224.05 h60
  text "MIL" at 12988.46,6224.05 h60
  text "7.874" at 12667.32,6102.36 h60
  text "MIN. CLEARANCE:" at 11737.46,6099.92 h60
  text "MIL" at 12988.46,6099.92 h60
  text "MIN. VIA PAD SIZE:" at 11737.46,5975.8 h60
  text "24" at 12803.71,5975.8 h60
  text "MIL" at 12988.46,5975.8 h60
  text "0.05mm (2MIL)" at 12432.46,5845.9 h60
  text "MINIMUM ANNULAR RING" at 11408.23,5837.67 h60
  text "EXTERNAL" at 13140.46,5837.67 h60
  text "PER" at 11608.23,5727.55 h60
  text "IPC-D-275 CLASS 2 LEVEL C" at 11828.23,5727.54 h60
  text "MIL, HOLES" at 13316.46,5627.07 h60
  text "+/-" at 12924,5618.48 h60
  text "+/-" at 13778,5618.48 h60
  text "REGISTRATION TOLERANCES:" at 11408.23,5617.42 h60
  text "METAL" at 12608,5617.42 h60
  text "5" at 13184.2,5617.42 h60
  text "3" at 14017.2,5617.42 h60
  text "MIL" at 14133.46,5617.42 h60
  text "HOLE SIZE TOLERANCE (UNLESS OTHERWISE SPECIFIED):" at 11408.23,5519.1 h60
  text "+/-" at 13778,5516.23 h60
  text "3" at 14017.2,5515.17 h60
  text "MIL" at 14133.46,5515.17 h60
  text "MATERIAL:" at 11333.46,5377.52 h60
  text "FR-4 High Tg" at 12319.9,5249 h60
  text "X" at 12175.46,5241.01 h60
  text "FR-408" at 11754.46,5236.49 h60
  text "OTHER" at 13242.46,5236.49 h60
  text "62 MIL (1.6mm) +/-10%" at 12074.56,5093.46 h60
  text "X" at 11954.46,5091.01 h60
  text "THICKNESS:" at 11408.23,5085.24 h60
  text "OTHER" at 13359.46,5085.24 h60
  text "TOLERANCE:" at 11408.23,4946.92 h60
  text "X" at 12256.46,4946.92 h60
  text "ANSI IPC-6012 TYPE 3 CLASS 2" at 12434.48,4946.92 h60
  text "OTHER +/-" at 12434.46,4802.73 h60
  text "BOW & TWIST:" at 11408.23,4657.54 h60
  text "X" at 12256.46,4657.54 h60
  text "ANSI IPC-6012 TYPE 3 CLASS 2" at 12434.48,4657.54 h60
  text "OTHER +/-" at 12434.46,4510.85 h60
  text "DRILLING:" at 11333.46,4380.23 h60
  text "NC_DRILL FILES" at 13094.46,4275.04 h60
  text "REFERENCE:" at 11408.23,4271.1 h60
  text "X" at 12065.46,4271.01 h60
  text "AS SHOWN" at 12243.46,4271.1 h60
  text "X" at 12966.46,4271.1 h60
  text "OTHER" at 13392.46,4128.85 h60
  text "PTH COPPER THICKNESS:" at 11407.91,4125.32 h60
  text "X" at 12547.14,4125.32 h60
  text "20-30 um" at 12675.14,4125.32 h60
  text "BOARD FINISH:" at 11333.46,3977.73 h60
  text "SILKSCREEN:" at 11488.68,3867.6 h60
  text "X" at 12446.46,3867.6 h60
  text "TOP" at 12563.46,3867.6 h60
  text "X" at 12956.46,3867.6 h60
  text "BOTTOM" at 13074.46,3867.6 h60
  text "SILKSCREEN COLOR:" at 11488.68,3712.41 h60
  text "X" at 12445.46,3712.41 h60
  text "WHITE" at 12563.46,3712.41 h60
  text "OTHER" at 13074.46,3712.41 h60
  text "X" at 12576.46,3568.96 h60
  text "GREEN" at 12694.46,3568.96 h60
  text "OTHER" at 13312.46,3568.96 h60
  text "SOLDER RESIST COLOR:" at 11488.68,3562.1 h60
  text "X" at 12576.46,3414.71 h60
  text "MATTE" at 12694.46,3414.71 h60
  text "SEMI-GLOSS" at 13312,3414.07 h60
  text "IMMERSION GOLD (ENIG)" at 12394.46,3241.94 h60
  text "ENEPIG" at 13732,3234.72 h60
  text "SURFACE FINISH:" at 11333.46,3233.72 h60
  text "X" at 12216.46,3233.72 h60
  text "IMM. TIN/SILVER OR EQUIV" at 11663,3096.4 h60
  text "OTHER" at 13094.46,3092.47 h60
  text "ARRAY/PANEL:" at 11333.46,2937.09 h60
  text "X" at 12216.46,2928.87 h60
  text "CUT AND TRIM PER M1 BOARD OUTLINE" at 12394.46,2928.87 h60
  text "N.C. ROUTE" at 12394.46,2792.9 h60
  text "V. SCORE" at 13260.46,2792.9 h60
  text "CERTIFICATION:" at 11333.46,2663.77 h60
  text "MATERIALS AND WORKMANSHIP FOR ALL PCBS" at 12058.46,2663.77 h60
  text "TO MEET OR EXCEED THE REQUIREMENTS OF:" at 12058.46,2569.71 h60
  text "X" at 11695.97,2441.08 h60
  text "ANSI IPC-A-600F CLASS ->" at 11823.96,2441.08 h60
  text "X" at 13471.97,2441.08 h60
  text "2" at 13581.96,2441.08 h60
  text "1" at 13266.96,2439.58 h60
  text "3" at 13935.96,2439.58 h60
  text "X" at 12507.97,2293.39 h60
  text "RoHS" at 12635.96,2293.39 h60
  text "OTHER" at 13280.36,2293.39 h60
  text "PER ORDER" at 13677.42,2293.39 h60
  text "ALL BOARDS MUST MEET OR EXCEED UL94-V0 REQUIREMENTS." at 11361,2139.57 h60
  text "PCB MUST BEAR THE UL94V-0 UL REGISTERED MATERIAL ID NUMBER" at 11361,2023.5 h60
  text "ADDITIONAL REQUIREMENTS:" at 11333.46,1854.08 h60
  text "MICROSECTION:" at 11408.23,1746.95 h60
  text "YES" at 12313.96,1746.95 h60
  text "REQUIRED" at 13175.46,1602.62 h60
  text "BARE BOARD ELEC. TEST:" at 11408.23,1599.76 h60
  text "NONE" at 12713.96,1599.76 h60
  text "X" at 13057.46,1599.76 h60
  text "PER ORDER" at 13767.46,1599.76 h60
  text "XX MIL VIAS REQUIRE NON-CONDUCTIVE FILL AND PLANARIZE" at 11576.38,1394.82 h59
  text "XX MIL VIAS REQUIRE CONDUCTIVE FILL AND PLANARIZE" at 11584.38,1290.84 h60
  text "OUTER XX MIL TRACES REQUIRE 50 OHM SINGLE-ENDED IMPEDANCE" at 11583.39,1127.46 h58
  text "LAYER 2 & 3 (INNER LAYERS) XX MIL WIDE, XX MIL SPACE / TRACES REQUIRE 100 OHM DIFFERENTIAL IMPEDANCE" at 11575.39,891.74 h60
  text ".Layer_Name" at 577,-858.49 h60
M11 Gerber Information:
  lines w10: -292,-930.17 6308,-930.17 ; -292,-726.83 6310,-726.83 ; -292,-523.5 -292,-1133.5 3713,-1133.5 6310,-1133.5 6310,-523.5 -291.5,-523.5 -291.5,-1133.5 1284,-1133.5 ; 2173,-1133.5 2173,-523.5 ; 3440,-726.83 3440,-523.5 ; 4280,-726.83 4280,-523.5 ; 4902,-1140 4902,-937.17
  text "ALL ARTWORK VIEWED FROM TOP SIDE" at -228.5,-655.67 h60
  text "BOARD #:" at 2248,-655.67 h60
  text ".PRJ_Number" at 2793.5,-655.67 h60
  text "REV:" at 3638,-655.67 h60
  text ".PCB_Rev" at 3929.5,-655.67 h60
  text "SVN REV:" at 4476,-655.67 h60
  text ".VersionControl_RevNumber" at 4982,-655.67 h60
  text "LAYER NAME =" at -228.5,-858.49 h60
  text "TID #:" at 2248,-859 h60
  text ".TID" at 2793.5,-859 h60
  text "PLOT NAME =" at -228.5,-1064.34 h60
  text ".plot_File_Name" at 577,-1064.34 h60
  text "GENERATED    :" at 2250,-1064.34 h60
  text ".Print_Date" at 3119.5,-1064.34 h60
  text ".Print_Time" at 3848.5,-1064.34 h60
  text "TEXAS INSTRUMENTS" at 5113,-1064.34 h60
M12 Stackup:
  drawing of 295 lines, arcs and shapes, not listed
  text "Layer" at 9821.59,7874.94 h60
  text "Name" at 10231.51,7874.94 h60
  text "Material" at 11161.25,7874.94 h60
  text "Thickness" at 12021.02,7874.94 h60
  text "Constant" at 12670.85,7874.94 h60
  text "Board Layer Stack" at 13240.71,7874.94 h60
  text "Top Overlay" at 10231.51,7754.94 h60
  text "Top Solder" at 10231.51,7634.94 h60
  text "Solder Resist" at 11161.25,7634.94 h60
  text "0.40mil" at 12021.02,7634.94 h60
  text "3.5" at 12670.85,7634.94 h60
  text "1" at 9821.59,7514.94 h60
  text "Top Layer" at 10231.51,7514.94 h60
  text "2.80mil" at 12021.02,7514.94 h60
  text "Dielectric 1" at 10231.51,7394.94 h60
  text "PP-006" at 11161.25,7394.94 h60
  text "2.80mil" at 12021.02,7394.94 h60
  text "4.1" at 12670.85,7394.94 h60
  text "2" at 9821.59,7274.94 h60
  text "Layer 1" at 10231.51,7274.94 h60
  text "CF-004" at 11161.25,7274.94 h60
  text "2.80mil" at 12021.02,7274.94 h60
  text "Dielectric1" at 10231.51,7154.94 h60
  text "FR-4 High Tg" at 11161.25,7154.94 h60
  text "59.20mil" at 12021.02,7154.94 h60
  text "4.8" at 12670.85,7154.94 h60
  text "3" at 9821.59,7034.94 h60
  text "Layer 2" at 10231.51,7034.94 h60
  text "CF-004" at 11161.25,7034.94 h60
  text "2.80mil" at 12021.02,7034.94 h60
  text "Dielectric 2" at 10231.51,6914.94 h60
  text "PP-006" at 11161.25,6914.94 h60
  text "2.80mil" at 12021.02,6914.94 h60
  text "4.1" at 12670.85,6914.94 h60
  text "4" at 9821.59,6794.94 h60
  text "Bottom Layer" at 10231.51,6794.94 h60
  text "2.80mil" at 12021.02,6794.94 h60
  text "Bottom Solder" at 10231.51,6674.94 h60
  text "Solder Resist" at 11161.25,6674.94 h60
  text "0.40mil" at 12021.02,6674.94 h60
  text "3.5" at 12670.85,6674.94 h60
  text "Bottom Overlay" at 10231.51,6554.94 h60
  text ".Layer_Name" at 577,-858.49 h60
M13 Component Bodies Top:
  text ".Layer_Name" at 577,-858.49 h60
M14 Component Bodies Bottom:
  text ".Layer_Name" at 577,-858.49 h60
M15 Courtyards Top:
  text ".Layer_Name" at 577,-858.49 h60
M16 Courtyards Bottom:
  text ".Layer_Name" at 577,-858.49 h60
Drill Drawing:
  lines w10: 4234.73,241.66 4251.4,241.66 4251.4,224.99 4284.73,224.99 4284.73,241.66 4301.4,241.66 4301.4,274.99 4284.73,274.99 4284.73,291.66 4251.4,291.66 4251.4,274.99 4234.73,274.99 4234.73,241.66 ; 4234.73,374.99 4234.73,391.66 4251.4,408.33 4234.73,424.99 4234.73,441.66 4251.4,441.66 4268.07,424.99 4284.73,441.66 4301.4,441.66 4301.4,424.99 4284.73,408.33 4301.4,391.66 4301.4,374.99 4284.73,374.99 4268.07,391.66 4251.4,374.99 4234.73,374.99 ; 4234.73,541.66 4251.4,541.66 4268.07,524.99 4284.73,541.66 4301.4,541.66 4284.73,558.33 4301.4,574.99 4284.73,574.99 4268.07,591.66 4251.4,574.99 4234.73,574.99 4251.4,558.33 4234.73,541.66 ; 4234.73,674.99 4268.07,691.66 4301.4,674.99 4284.73,708.33 4301.4,741.66 4268.07,724.99 4234.73,741.66 4251.4,708.33 4234.73,674.99 ; 4234.73,824.99 4301.4,824.99 4301.4,891.66 4234.73,891.66 4234.73,824.99 ; 4234.73,974.99 4301.4,974.99 4301.4,1041.66 4234.73,1041.66 4234.73,974.99 ; 4234.73,1191.66 4301.4,1191.66 4268.07,1124.99 4234.73,1191.66 ; 4248.07,838.33 4288.07,838.33 4288.07,878.33 4248.07,878.33 4248.07,838.33
  lines w15: 4174.94,179.99 11245.03,179.99 ; 4174.94,1229.99 11245.03,1229.99 ; 4725.82,29.99 4725.82,1379.99 ; 5325.66,29.99 5325.66,1379.99 ; 6475.32,29.99 6475.32,1379.99 ; 6981.2,29.99 6981.2,1379.99 ; 7715,29.99 7715,1379.99 ; 9214.55,29.99 9214.55,1379.99 ; 9804.4,29.99 9804.4,1379.99 ; 10550.2,29.99 10550.2,1379.99 ; 4174.94,29.99 11245.03,29.99 11245.03,1379.99 4174.94,1379.99 4174.94,29.99
  text "Symbol" at 4264.94,1274.99 h72
  text "Count" at 4770.82,1274.99 h72
  text "Hole Size" at 5370.66,1274.99 h72
  text "Plated" at 6520.32,1274.99 h72
  text "Hole Type" at 7026.2,1274.99 h72
  text "Drill Layer Pair" at 7760,1274.99 h72
  text "Via/Pad" at 9259.55,1274.99 h72
  text "Pad Shape" at 9849.4,1274.99 h72
  text "Template" at 10595.2,1274.99 h72
  text "4" at 4770.82,1124.99 h60
  text "40.00mil (1.016mm)" at 5370.66,1124.99 h60
  text "PTH" at 6520.32,1124.99 h60
  text "Round" at 7026.2,1124.99 h60
  text "Top Layer - Bottom Layer" at 7760,1124.99 h60
  text "Pad" at 9259.55,1124.99 h60
  text "(Mixed)" at 9849.4,1124.99 h60
  text "(Mixed)" at 10595.2,1124.99 h60
  text "4" at 4770.82,974.99 h60
  text "59.06mil (1.500mm)" at 5370.66,974.99 h60
  text "PTH" at 6520.32,974.99 h60
  text "Round" at 7026.2,974.99 h60
  text "Top Layer - Bottom Layer" at 7760,974.99 h60
  text "Pad" at 9259.55,974.99 h60
  text "(Mixed)" at 9849.4,974.99 h60
  text "(Mixed)" at 10595.2,974.99 h60
  text "4" at 4770.82,824.99 h60
  text "100.39mil (2.550mm)" at 5370.66,824.99 h60
  text "PTH" at 6520.32,824.99 h60
  text "Round" at 7026.2,824.99 h60
  text "Top Layer - Bottom Layer" at 7760,824.99 h60
  text "Pad" at 9259.55,824.99 h60
  text "(Mixed)" at 9849.4,824.99 h60
  text "(Mixed)" at 10595.2,824.99 h60
  text "6" at 4770.82,674.99 h60
  text "50.00mil (1.270mm)" at 5370.66,674.99 h60
  text "PTH" at 6520.32,674.99 h60
  text "Round" at 7026.2,674.99 h60
  text "Top Layer - Bottom Layer" at 7760,674.99 h60
  text "Pad" at 9259.55,674.99 h60
  text "(Mixed)" at 9849.4,674.99 h60
  text "(Mixed)" at 10595.2,674.99 h60
  text "8" at 4770.82,524.99 h60
  text "7.87mil (0.200mm)" at 5370.66,524.99 h60
  text "PTH" at 6520.32,524.99 h60
  text "Round" at 7026.2,524.99 h60
  text "Top Layer - Bottom Layer" at 7760,524.99 h60
  text "Via" at 9259.55,524.99 h60
  text "Rounded" at 9849.4,524.99 h60
  text "(Mixed)" at 10595.2,524.99 h60
  text "51" at 4770.82,374.99 h60
  text "12.00mil (0.305mm)" at 5370.66,374.99 h60
  text "PTH" at 6520.32,374.99 h60
  text "Round" at 7026.2,374.99 h60
  text "Top Layer - Bottom Layer" at 7760,374.99 h60
  text "Via" at 9259.55,374.99 h60
  text "Rounded" at 9849.4,374.99 h60
  text "v76h30" at 10595.2,374.99 h60
  text "148" at 4770.82,224.99 h60
  text "18.00mil (0.457mm)" at 5370.66,224.99 h60
  text "PTH" at 6520.32,224.99 h60
  text "Round" at 7026.2,224.99 h60
  text "Top Layer - Bottom Layer" at 7760,224.99 h60
  text "Via" at 9259.55,224.99 h60
  text "Rounded" at 9849.4,224.99 h60
  text "v102h46" at 10595.2,224.99 h60
  text "225 Total" at 4770.82,74.99 h60
  text ".Layer_Name" at 577,-858.49 h60
M17 Embedded Cavity:
  text ".Layer_Name" at 577,-858.49 h60
M18 Embedded Assembly:
  text ".Layer_Name" at 577,-858.49 h60
M19 Embedded Keepout:
  text ".Layer_Name" at 577,-858.49 h60

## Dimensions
0,0 to 0,3800 on M2 Board Dimensions
0,0 to 4000,0 on M2 Board Dimensions
0,-400 to 1000,-400 on M2 Board Dimensions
